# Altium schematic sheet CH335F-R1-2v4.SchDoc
size 209 x 148 mm; PageSetup: Record=PageOptions¦CenterHorizontal=True¦CenterVertical=True¦PrintScale=0.65¦XCorrection=1.00¦YCorrection=1.00¦PrintKind=1¦BorderSize=5000000¦LeftOffset=0¦BottomOffset=0¦Orientation=2¦PaperLength=1000¦PaperWidth=1000¦Scale=100¦PaperSource=7¦PrintQuality=-4¦MediaType=1¦DitherType=10¦PaperKind=16 开 195x270¦PrintScaleMode=1
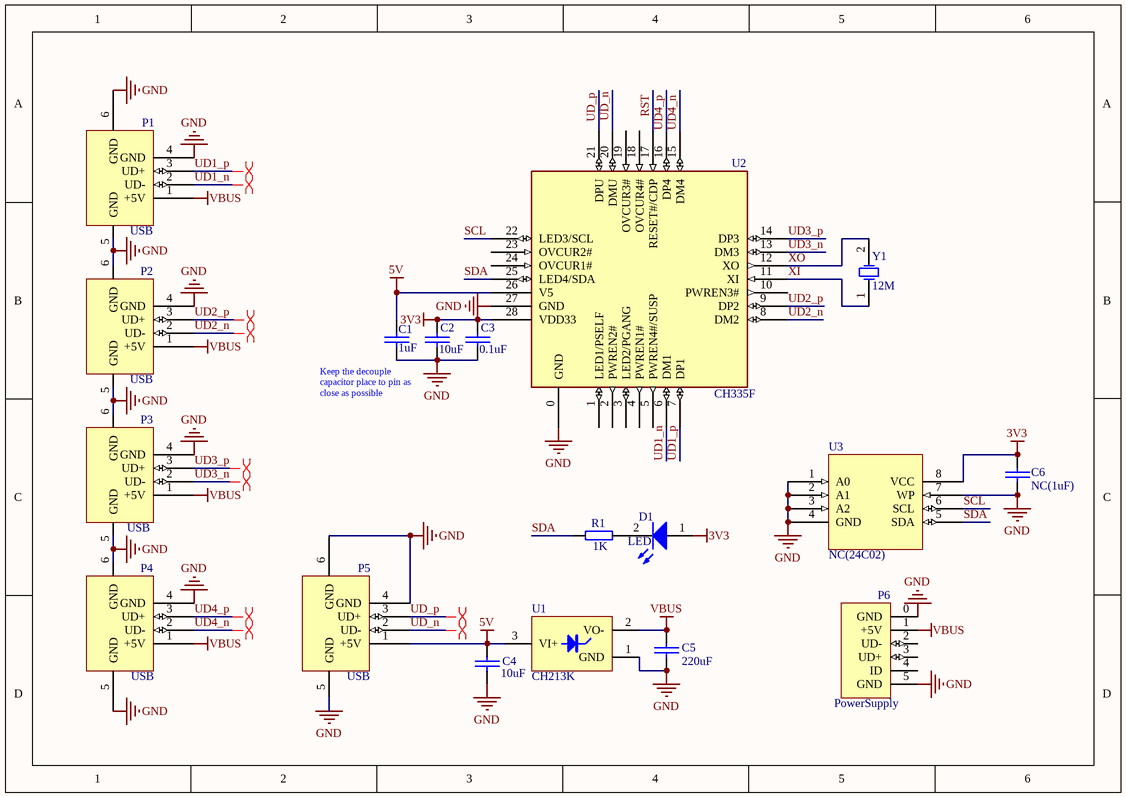
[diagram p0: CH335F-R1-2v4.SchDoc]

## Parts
C1  1uF  [0603_C]
C2  10uF  [0603_C]
C3  0.1uF  [0603_C]
C4  10uF  [0603_C]
C5  220uF  [CD0.1]
C6  NC(1uF)  [0603_C]
D1  LED  [0603+]
P1  USB  [USBAF]
P2  USB  [USB2.0-A-F-TH_4P-V_13.7mm]
P3  USB  [USB2.0-A-F-TH_4P-V_13.7mm]
P4  USB  [USB2.0-A-F-TH_4P-V_13.7mm]
P5  USB  [USBAF]
P6  PowerSupply  [USBMICROB-02-GXPX-A1T2]
R1  1K  [0603_R]
U1  CH213K  [SOT-23-3]
U2  CH335F  [QFN28_4X4]
U3  NC(24C02)  [SOIC-8_150mil]
Y1  12M  [XT_AT49]

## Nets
3V3: C2.1 C3.1 C6.2 D1.1(A) U2.28(VDD33) U3.8(VCC)
5V: C1.1 C4.1 P5.1(+5V) U1.3(VI+) U2.26(V5)
GND: C1.2 C2.2 C3.2 C4.2 C5.2 C6.1 P1.4(GND) P1.5(GND) P1.6(GND) P2.4(GND) P2.5(GND) P2.6(GND) P3.4(GND) P3.5(GND) P3.6(GND) P4.4(GND) P4.5(GND) P4.6(GND) P5.4(GND) P5.5(GND) P5.6(GND) P6.0(GND) P6.5(GND) U1.1(GND) U2.0(GND) U2.27(GND) U3.1(A0) U3.2(A1) U3.3(A2) U3.4(GND) U3.7(WP)
VBUS: C5.1 P1.1(+5V) P2.1(+5V) P3.1(+5V) P4.1(+5V) P6.1(+5V) U1.2(VO-)
RST: U2.17(RESET#/CDP)
SCL: U2.22(LED3/SCL) U3.6(SCL)
SDA: R1.1 U2.25(LED4/SDA) U3.5(SDA)
UD1_n: P1.2(UD-) U2.6(DM1)
UD1_p: P1.3(UD+) U2.7(DP1)
UD2_n: P2.2(UD-) U2.8(DM2)
UD2_p: P2.3(UD+) U2.9(DP2)
UD3_n: P3.2(UD-) U2.13(DM3)
UD3_p: P3.3(UD+) U2.14(DP3)
UD4_n: P4.2(UD-) U2.15(DM4)
UD4_p: P4.3(UD+) U2.16(DP4)
UD_n: P5.2(UD-) U2.20(DMU)
UD_p: P5.3(UD+) U2.21(DPU)
XI: U2.11(XI) Y1.1(OSC1)
XO: U2.12(XO) Y1.2(OSC2)
NetD1_2: D1.2(K) R1.2

Not connected (* = marked no-connect by the designer): P6 2(UD-) 3(UD+) 4(ID); U2 1(LED1/PSELF) 2(PWREN2#) 3(LED2/PGANG) 4(PWREN1#) 5(PWREN4#/SUSP) 10(PWREN3#) 18(OVCUR4#) 19(OVCUR3#) 23(OVCUR2#) 24(OVCUR1#)

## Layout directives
differential pair: UD1_n, UD1_p, UD2_n, UD2_p, UD3_n, UD3_p, UD4_n, UD4_p, UD_n, UD_p

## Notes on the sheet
- Keep the decouple capacitor place to pin as close as possible

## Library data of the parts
C1-C6 = CAP: Capacitor
D1 = LED: Typical INFRARED GaAs LED
P1-P5 = USB: USB Port
P6 = MicroUSB: MicroUSB Port
R1 = RES
U1 = CH213K: Ideal Diode 5V*1A
U2 = CH335F: 4 ports High-Speed USB MTT Hub with 4 over current detect & power control
U3 = 24C01
Y1 = XTAL: Crystal Oscillator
